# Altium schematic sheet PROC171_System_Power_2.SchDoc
size 431 x 279 mm; Date: Not shown in title block; ApprovedBy: Not shown in title block; CheckedBy: Not shown in title block; Author: Not shown in title block; CompanyName: Not shown in title block; Engineer: Not shown in title block; Organization: Not shown in title block; Address1: Not shown in title block; Address2: Not shown in title block; Address3: Not shown in title block; Address4: Not shown in title block; DocumentNumber: 4; Revision: Use project parameter SCH_Rev; SheetNumber: 4; SheetTotal: 27; PageSetup: Record=PageOptions¦CenterHorizontal=True¦CenterVertical=True¦PrintScale=1.00¦XCorrection=1.00¦YCorrection=1.00¦PrintKind=0¦BorderSize=5000000¦LeftOffset=0¦BottomOffset=0¦Orientation=2¦PaperLength=1000¦PaperWidth=1000¦Scale=100¦PaperSource=15¦PrintQuality=600¦MediaType=1¦DitherType=10¦PaperKind=Letter¦PrintScaleMode=1
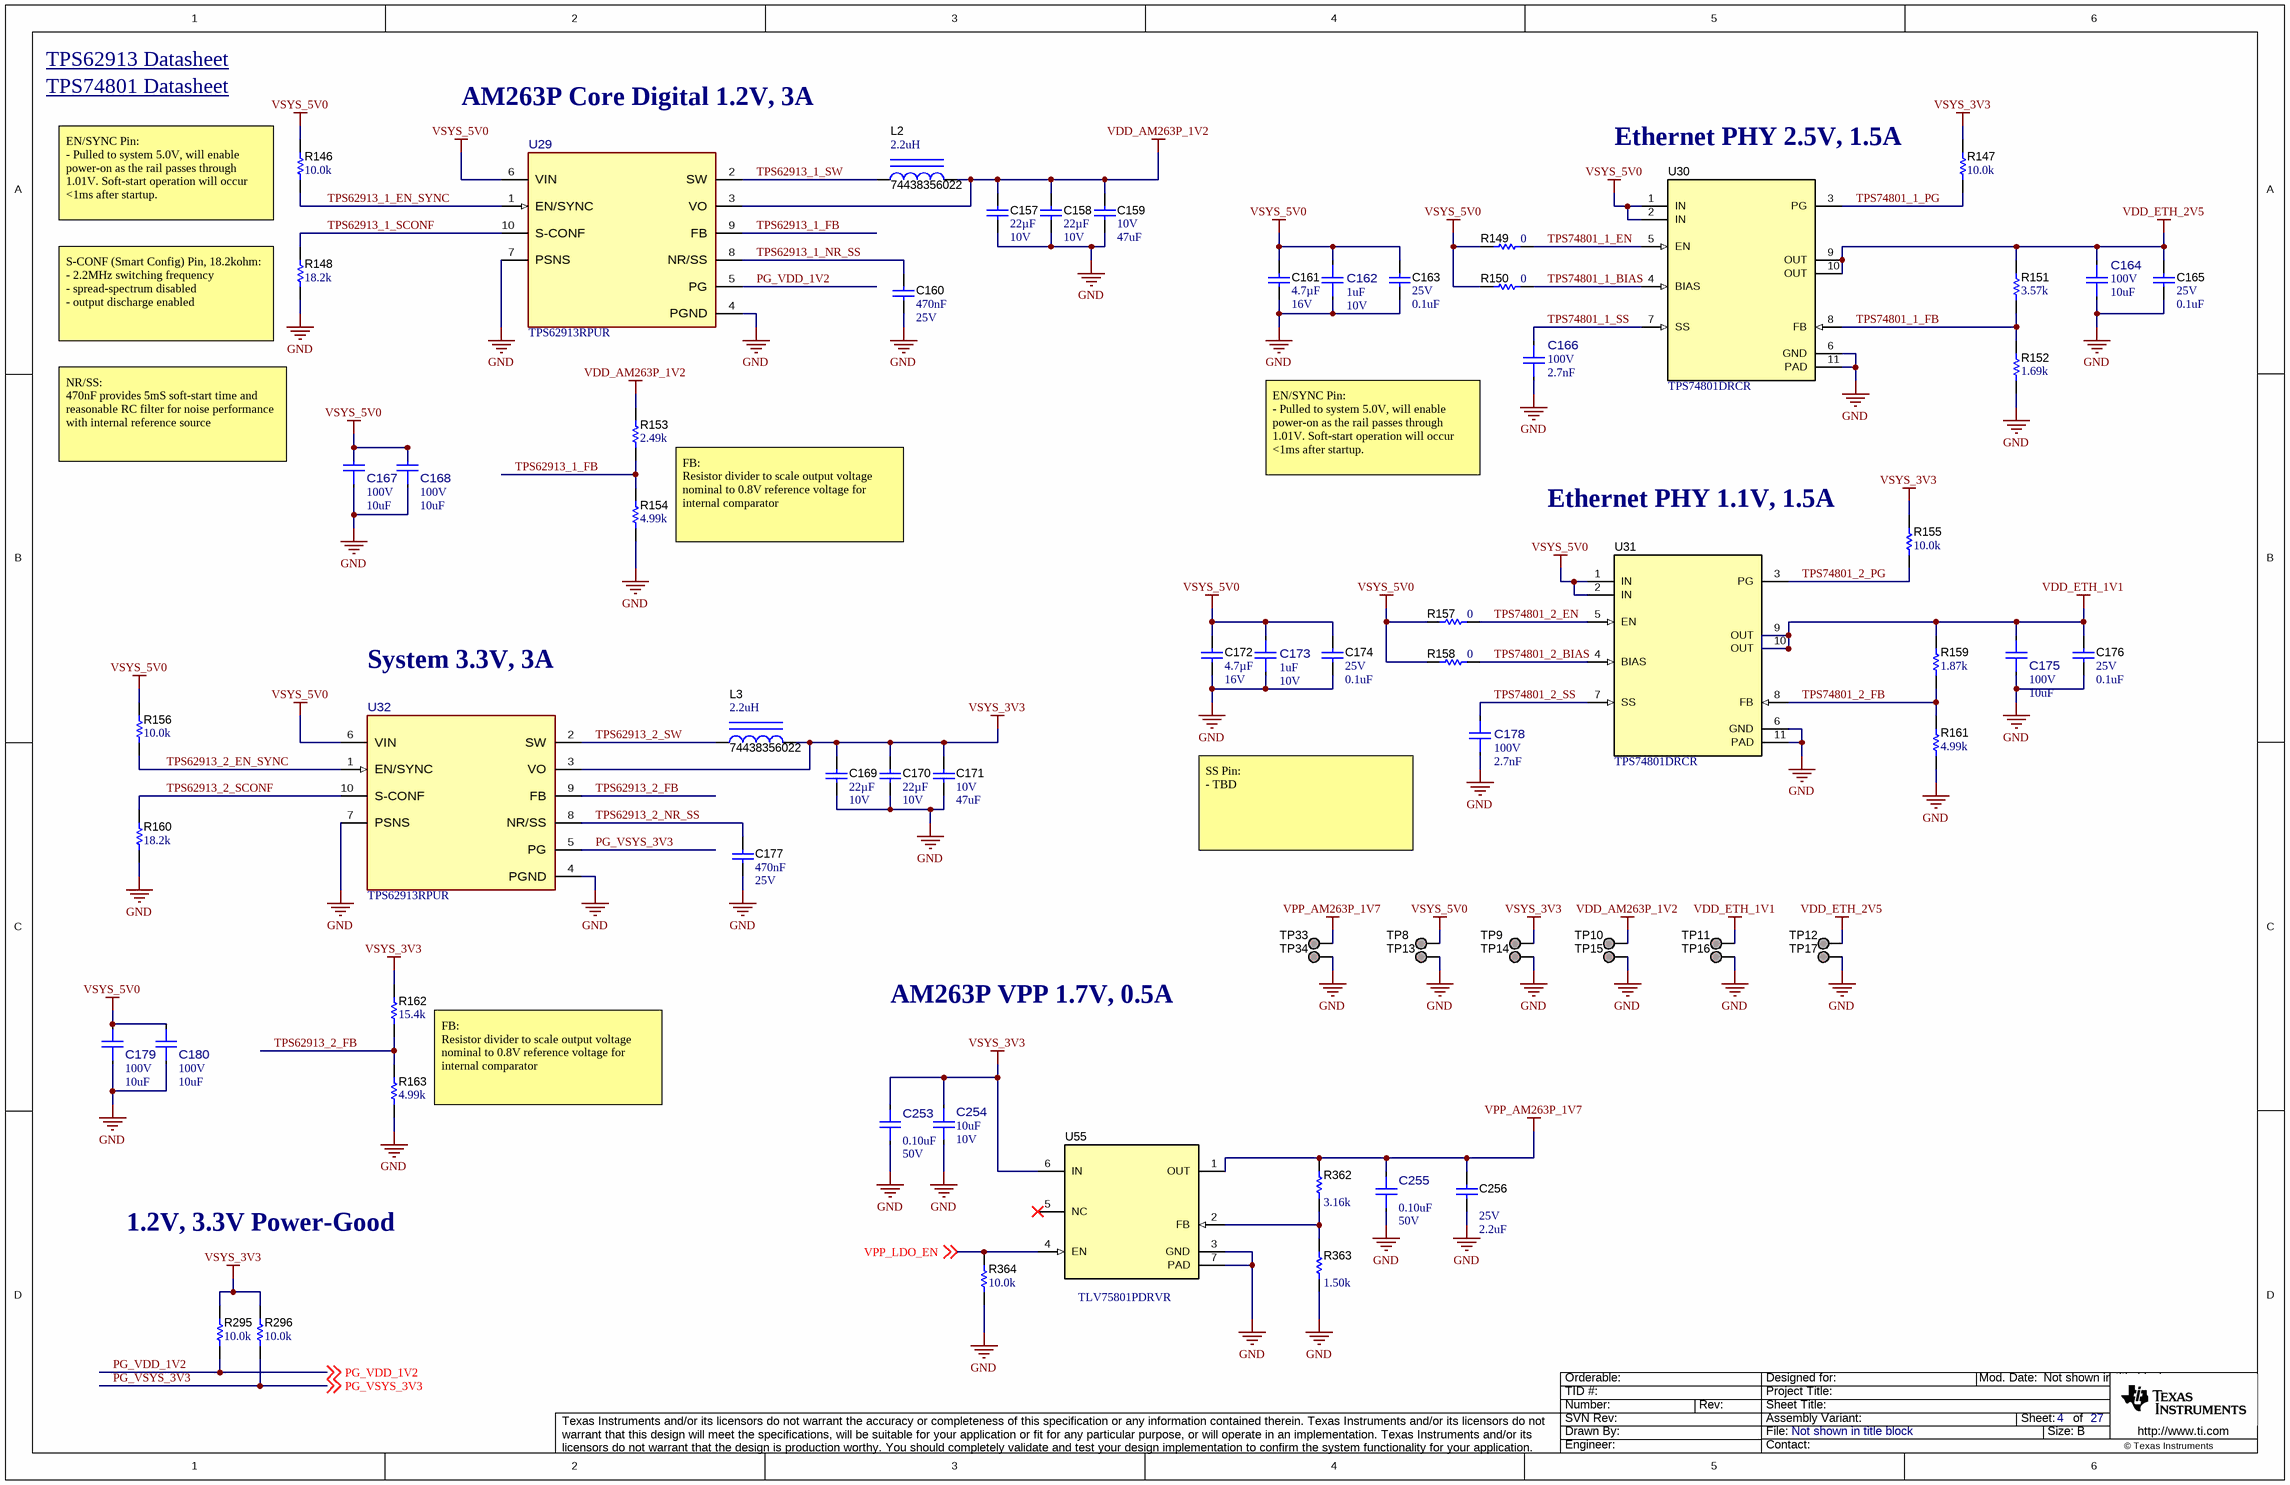
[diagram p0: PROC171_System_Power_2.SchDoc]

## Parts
C157  Cap_F: 22µF  VDC_V: 10V  [0805_HV]  (hidden comment: GRM21BZ71A226ME15L)
C158  Cap_F: 22µF  VDC_V: 10V  [0805_HV]  (hidden comment: GRM21BZ71A226ME15L)
C159  VDC_V: 10V  ValueDisplayed: 47uF  [1210_270]  (hidden comment: GRM32ER71A476ME15L)
C160  Cap_F: 470nF  VDC_V: 25V  [0603]  (hidden comment: GRM188R71E474KA12D)
C161  Cap_F: 4.7µF  VDC_V: 16V  [0603]  (hidden comment: GRM188Z71C475KE21D)
C162  ValueDisplayed: 1uF  VDC_V: 10V  [FP-GRM155C71A105KE11D_0402-MFG]  (hidden comment: GRM155C71A105KE11D)
C163  VDC_V: 25V  ValueDisplayed: 0.1uF  [0402]  (hidden comment: GRM155R71E104KE14D)
C164  VDC_V: 100V  ValueDisplayed: 10uF  [FP-GRM32EC72A106KE05L_1210-MFG]  (hidden comment: GRM32EC72A106KE05L)
C165  VDC_V: 25V  ValueDisplayed: 0.1uF  [0402]  (hidden comment: GRM155R71E104KE14D)
C166  VDC_V: 100V  ValueDisplayed: 2.7nF  [FP-GCM155R72A272KA37D_0402-MFG]  (hidden comment: GCM155R72A272KA37D)
C167  VDC_V: 100V  ValueDisplayed: 10uF  [FP-GRM32EC72A106KE05L_1210-MFG]  (hidden comment: GRM32EC72A106KE05L)
C168  VDC_V: 100V  ValueDisplayed: 10uF  [FP-GRM32EC72A106KE05L_1210-MFG]  (hidden comment: GRM32EC72A106KE05L)
C169  Cap_F: 22µF  VDC_V: 10V  [0805_HV]  (hidden comment: GRM21BZ71A226ME15L)
C170  Cap_F: 22µF  VDC_V: 10V  [0805_HV]  (hidden comment: GRM21BZ71A226ME15L)
C171  VDC_V: 10V  ValueDisplayed: 47uF  [1210_270]  (hidden comment: GRM32ER71A476ME15L)
C172  Cap_F: 4.7µF  VDC_V: 16V  [0603]  (hidden comment: GRM188Z71C475KE21D)
C173  ValueDisplayed: 1uF  VDC_V: 10V  [FP-GRM155C71A105KE11D_0402-MFG]  (hidden comment: GRM155C71A105KE11D)
C174  VDC_V: 25V  ValueDisplayed: 0.1uF  [0402]  (hidden comment: GRM155R71E104KE14D)
C175  VDC_V: 100V  ValueDisplayed: 10uF  [FP-GRM32EC72A106KE05L_1210-MFG]  (hidden comment: GRM32EC72A106KE05L)
C176  VDC_V: 25V  ValueDisplayed: 0.1uF  [0402]  (hidden comment: GRM155R71E104KE14D)
C177  Cap_F: 470nF  VDC_V: 25V  [0603]  (hidden comment: GRM188R71E474KA12D)
C178  VDC_V: 100V  ValueDisplayed: 2.7nF  [FP-GCM155R72A272KA37D_0402-MFG]  (hidden comment: GCM155R72A272KA37D)
C179  VDC_V: 100V  ValueDisplayed: 10uF  [FP-GRM32EC72A106KE05L_1210-MFG]  (hidden comment: GRM32EC72A106KE05L)
C180  VDC_V: 100V  ValueDisplayed: 10uF  [FP-GRM32EC72A106KE05L_1210-MFG]  (hidden comment: GRM32EC72A106KE05L)
C253  ValueDisplayed: 0.10uF  VDC_V: 50V  [FP-GRM155R71H104KE14D_0402-MFG]  (hidden comment: GRM155R71H104KE14D)
C254  ValueDisplayed: 10uF  VDC_V: 10V  [FP-KGM05CR51A106MH_0402-MFG]  (hidden comment: KGM05CR51A106MH)
C255  ValueDisplayed: 0.10uF  VDC_V: 50V  [FP-GRM155R71H104KE14D_0402-MFG]  (hidden comment: GRM155R71H104KE14D)
C256  VDC_V: 25V  ValueDisplayed: 2.2uF  [0402_070]  (hidden comment: GRM155R61E225KE11D)
L2  74438356022  ValueDisplayed: 2.2uH  [WE-MAPI_4020]
L3  74438356022  ValueDisplayed: 2.2uH  [WE-MAPI_4020]
R146  ValueDisplayed: 10.0k  [0402]  (hidden comment: ERJ-2RKF1002X)
R147  ValueDisplayed: 10.0k  [0402]  (hidden comment: ERJ-2RKF1002X)
R148  ValueDisplayed: 18.2k  [0805_HV]  (hidden comment: ERJ-6ENF1822V)
R149  ValueDisplayed: 0  [0402]  (hidden comment: ERJ-2GE0R00X)
R150  ValueDisplayed: 0  [0402]  (hidden comment: ERJ-2GE0R00X)
R151  ValueDisplayed: 3.57k  [0402]  (hidden comment: CRCW04023K57FKED)
R152  ValueDisplayed: 1.69k  [0402]  (hidden comment: CRCW04021K69FKED)
R153  ValueDisplayed: 2.49k  [0402]  (hidden comment: CRCW04022K49FKED)
R154  ValueDisplayed: 4.99k  [0402]  (hidden comment: CRCW04024K99FKED)
R155  ValueDisplayed: 10.0k  [0402]  (hidden comment: ERJ-2RKF1002X)
R156  ValueDisplayed: 10.0k  [0402]  (hidden comment: ERJ-2RKF1002X)
R157  ValueDisplayed: 0  [0402]  (hidden comment: ERJ-2GE0R00X)
R158  ValueDisplayed: 0  [0402]  (hidden comment: ERJ-2GE0R00X)
R159  ValueDisplayed: 1.87k  [0402]  (hidden comment: CRCW04021K87FKED)
R160  ValueDisplayed: 18.2k  [0805_HV]  (hidden comment: ERJ-6ENF1822V)
R161  ValueDisplayed: 4.99k  [0402]  (hidden comment: CRCW04024K99FKED)
R162  ValueDisplayed: 15.4k  [0402]  (hidden comment: CRCW040215K4FKED)
R163  ValueDisplayed: 4.99k  [0402]  (hidden comment: CRCW04024K99FKED)
R295  ValueDisplayed: 10.0k  [0402]  (hidden comment: ERJ-2RKF1002X)
R296  ValueDisplayed: 10.0k  [0402]  (hidden comment: ERJ-2RKF1002X)
R362  ValueDisplayed: 3.16k  [0603]  (hidden comment: RC0603FR-073K16L)
R363  ValueDisplayed: 1.50k  [0402]  (hidden comment: CRCW04021K50FKED)
R364  ValueDisplayed: 10.0k  [0402]  (hidden comment: ERJ-2RKF1002X)
TP8  TESTPOINT  [TP_25MIL-SMT]  (value not drawn)  (no BOM)
TP9  TESTPOINT  [TP_25MIL-SMT]  (value not drawn)  (no BOM)
TP10  TESTPOINT  [TP_25MIL-SMT]  (value not drawn)  (no BOM)
TP11  TESTPOINT  [TP_25MIL-SMT]  (value not drawn)  (no BOM)
TP12  TESTPOINT  [TP_25MIL-SMT]  (value not drawn)  (no BOM)
TP13  TESTPOINT  [TP_25MIL-SMT]  (value not drawn)  (no BOM)
TP14  TESTPOINT  [TP_25MIL-SMT]  (value not drawn)  (no BOM)
TP15  TESTPOINT  [TP_25MIL-SMT]  (value not drawn)  (no BOM)
TP16  TESTPOINT  [TP_25MIL-SMT]  (value not drawn)  (no BOM)
TP17  TESTPOINT  [TP_25MIL-SMT]  (value not drawn)  (no BOM)
TP33  TESTPOINT  [TP_25MIL-SMT]  (value not drawn)  (no BOM)
TP34  TESTPOINT  [TP_25MIL-SMT]  (value not drawn)  (no BOM)
U29  TPS62913RPUR  [RPU0010A-MFG]
U30  TPS74801DRCR  [DRC0010J]
U31  TPS74801DRCR  [DRC0010J]
U32  TPS62913RPUR  [RPU0010A-MFG]
U55  TLV75801PDRVR  [DRV0006A]

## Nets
GND: C157.2 C158.2 C159.2 C160.2 C161.2 C162.1 C163.2 C164.1 C165.2 C166.1 C167.1 C168.1 C169.2 C170.2 C171.2 C172.2 C173.1 C174.2 C175.1 C176.2 C177.2 C178.1 C179.1 C180.1 C253.1 C254.2 C255.1 C256.2 R148.1 R152.1 R154.1 R160.1 R161.1 R163.1 R363.1 R364.1 TP13.1 TP14.1 TP15.1 TP16.1 TP17.1 TP34.1 U29.4(PGND) U29.7(PSNS) U30.6(GND) U30.11(PAD) U31.6(GND) U31.11(PAD) U32.4(PGND) U32.7(PSNS) U55.3(GND) U55.7(PAD)
VDD_AM263P_1V2: C157.1 C158.1 C159.1 L2.2 R153.2 TP10.1 U29.3(VO)
VDD_ETH_1V1: C175.2 C176.1 R159.2 TP11.1 U31.9(OUT) U31.10(OUT)
VDD_ETH_2V5: C164.2 C165.1 R151.2 TP12.1 U30.9(OUT) U30.10(OUT)
VPP_AM263P_1V7: C255.2 C256.1 R362.2 TP33.1 U55.1(OUT)
VSYS_3V3: C169.1 C170.1 C171.1 C253.2 C254.1 L3.2 R147.2 R155.2 R162.2 R295.2 R296.2 TP9.1 U32.3(VO) U55.6(IN)
VSYS_5V0: C161.1 C162.2 C163.1 C167.2 C168.2 C172.1 C173.2 C174.1 C179.2 C180.2 R146.2 R149.1 R150.1 R156.2 R157.1 R158.1 TP8.1 U29.6(VIN) U30.1(IN) U30.2(IN) U31.1(IN) U31.2(IN) U32.6(VIN)
PG_VDD_1V2: R295.1 U29.5(PG) ; off-sheet PG_VDD_1V2
PG_VSYS_3V3: R296.1 U32.5(PG) ; off-sheet PG_VSYS_3V3
TPS62913_1_EN_SYNC: R146.1 U29.1(EN/SYNC)
TPS62913_1_FB: R153.1 R154.2 U29.9(FB)
TPS62913_1_NR_SS: C160.1 U29.8(NR/SS)
TPS62913_1_SCONF: R148.2 U29.10(S-CONF)
TPS62913_1_SW: L2.1 U29.2(SW)
TPS62913_2_EN_SYNC: R156.1 U32.1(EN/SYNC)
TPS62913_2_FB: R162.1 R163.2 U32.9(FB)
TPS62913_2_NR_SS: C177.1 U32.8(NR/SS)
TPS62913_2_SCONF: R160.2 U32.10(S-CONF)
TPS62913_2_SW: L3.1 U32.2(SW)
TPS74801_1_BIAS: R150.2 U30.4(BIAS)
TPS74801_1_EN: R149.2 U30.5(EN)
TPS74801_1_FB: R151.1 R152.2 U30.8(FB)
TPS74801_1_PG: R147.1 U30.3(PG)
TPS74801_1_SS: C166.2 U30.7(SS)
TPS74801_2_BIAS: R158.2 U31.4(BIAS)
TPS74801_2_EN: R157.2 U31.5(EN)
TPS74801_2_FB: R159.1 R161.2 U31.8(FB)
TPS74801_2_PG: R155.1 U31.3(PG)
TPS74801_2_SS: C178.2 U31.7(SS)
VPP_LDO_EN: R364.2 U55.4(EN) ; off-sheet VPP_LDO_EN
NetR362_1: R362.1 R363.2 U55.2(FB)

Not connected (* = marked no-connect by the designer): U55 5(NC)*

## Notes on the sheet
- TPS74801 Datasheet <https://www.ti.com/store/ti/en/p/product/?p=TPS74801DRCR>
- TPS62913 Datasheet <https://www.ti.com/product/TPS62913>
- AM263P Core Digital 1.2V, 3A
- Ethernet PHY 2.5V, 1.5A
- (near R146) EN/SYNC Pin:
  - Pulled to system 5.0V, will enable power-on as the rail passes through 1.01V. Soft-start operation will occur <1ms after startup.
- (near R148) S-CONF (Smart Config) Pin, 18.2kohm:
  - 2.2MHz switching frequency
  - spread-spectrum disabled
  - output discharge enabled
- NR/SS:
  470nF provides 5mS soft-start time and reasonable RC filter for noise performance with internal reference source
- EN/SYNC Pin:
  - Pulled to system 5.0V, will enable power-on as the rail passes through 1.01V. Soft-start operation will occur <1ms after startup.
- FB:
  Resistor divider to scale output voltage nominal to 0.8V reference voltage for internal comparator
- Ethernet PHY 1.1V, 1.5A
- System 3.3V, 3A
- SS Pin:
  - TBD
- AM263P VPP 1.7V, 0.5A
- 1.2V, 3.3V Power-Good

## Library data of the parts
C157 C158 C169 C170 = CMP-0008377-2: CAP, CERM, 22 uF, 10 V, +/- 20%, X7R, 0805; Manufacturer: MuRata; SizeY_mm: 1.25; Cap_Case: 0805; SizeArea_mm2: 2.5; AEC Qualified: N; AEC Category: Q200; ValueDisplayed: 22uF; TaMin_C: -55°C; SizeAreaWB_mm2: 6.75; Value1: Unknown; U/M: EA; Value: 22uF; TaMax_C: 125°C; SizeZ_mm: 1.45; SizeX_mm: 2
C159 C171 = CMP-0009221-2: CAP, CERM, 47 uF, 10 V, +/- 20%, X7R, 1210; Manufacturer: MuRata; TaMin_C: -55°C; Polarized: N; SizeAreaWB_mm2: 14.7; Value1: Unknown; U/M: EA; Value: 47uF; TaMax_C: 125°C; SizeZ_mm: 2.7; SizeX_mm: 3.2; SizeY_mm: 2.5; Cap_Case: 1210; SizeArea_mm2: 8; Cap_F: 47µF; AEC Category: Q200
C160 C177 = CMP-0007424-4: CAP, CERM, 0.47 uF, 25 V, +/- 10%, X7R, 0603; Manufacturer: MuRata; TaMin_C: -55°C; Polarized: N; SizeAreaWB_mm2: 4.68; Value1: Unknown; U/M: EA; Value: 0.47uF; TaMax_C: 125°C; SizeZ_mm: 1; SizeX_mm: 1.6; SizeY_mm: 0.8; SizeArea_mm2: 1.28; AEC Category: Q200
C161 C172 = CMP-0064936-4: CAP, CERM, 4.7 uF, 16 V,+/- 10%, X7R, 0603; Manufacturer: MuRata; TaMin_C: -55°C; Polarized: N; SizeAreaWB_mm2: 4.68; Value1: Unknown; U/M: EA; Value: 4.7uF; TaMax_C: 125°C; SizeZ_mm: 1; SizeX_mm: 1.6; SizeY_mm: 0.8; SizeArea_mm2: 1.28; AEC Category: Q200
C162 C173 = CMP-0035346-1: 1µF ±10% 10V Ceramic Capacitor X7S 0402 (1005 Metric); Manufacturer: Murata; AEC Qualified: No; SizeZ_mm: 0.6mm; TempCo: 22%
C163 C165 C174 C176 = CMP-0006659-2: CAP, CERM, 0.1 uF, 25 V, +/- 10%, X7R, 0402; Manufacturer: MuRata; TaMin_C: -55°C; Polarized: N; SizeAreaWB_mm2: 3; Value1: Unknown; U/M: EA; Value: 0.1uF; TaMax_C: 125°C; SizeZ_mm: 0.6; SizeX_mm: 1; SizeY_mm: 0.5; Cap_F: 100nF; AEC Category: Q200
C164 C167 C168 C175 C179 C180 = CMP-0087970-1: 10µF ±10% 100V Ceramic Capacitor X7S 1210 (3225 Metric); Manufacturer: Murata; TempCo: 22%; SizeZ_mm: 2.7mm; AEC Qualified: No; Symbol Name: SYM-GRM32EC72A106KE05L
C166 C178 = CMP-0035196-1: Ceramic Capacitor for Automotive 2.7nF ±10% 100VDC X7R 0402 Paper T/R; Manufacturer: Murata; TempCo: 15%; Tolerance_%: 0.1%; SizeZ_mm: 0.55mm; AEC Qualified: Yes; AEC Grade: Grade 1
C253 C255 = CMP-0096855-1: Chip Multilayer Ceramic Capacitors for General Purpose, 0402, 0.10uF, X7R, 15%, 10%, 50V; Manufacturer: Murata; SizeZ_mm: 0.55mm; Value: 100nF; AEC Qualified: No
C254 = CMP-0043010-1: 10 µF ±20% 10V Ceramic Capacitor X5R 0402 (1005 Metric); Manufacturer: KYOCERA AVX; AEC Qualified: No; Cap_F: 10µF; SizeZ_mm: 0.7mm; TempCo: 15%; Value: 10µF
C256 = CMP-0006610-2: CAP, CERM, 2.2 uF, 25 V, +/- 10%, X5R, 0402; Manufacturer: MuRata; TaMin_C: -55°C; Polarized: N; SizeAreaWB_mm2: 3; Value1: Unknown; U/M: EA; Value: 2.2uF; TaMax_C: 85°C; SizeZ_mm: 0.7; SizeX_mm: 1; SizeY_mm: 0.5; Cap_Case: 0402; Cap_F: 2.2µF; AEC Category: Q200
L2 L3 = CMP-0064169-1: Inductor, Shielded, 2.2 uH, 4.7 A, 0.029 ohm, SMD; Manufacturer: Wurth Elektronik; Isat: 6.2A @ 20% inductance drop; Irms: 4.7A @ 40C rise; Green_Lifecycle: Active; SizeAreaWB_mm2: 26.01; DCR_ohm: 29m; Green_REACh: Passed; Value: 2.2uH; Imax_A: 4.7A; SizeZ_mm: 2.1; SizeX_mm: 4.1; SizeArea_mm2: 16.81; Ind_H: 2.2µH; AEC Qualified: N; AEC Category: Q200
R146 R147 R155 R156 R295 R296 R364 = CMP-0026658-1: RES, 10.0 k, 1%, 0.1 W, 0402; Manufacturer: Panasonic; Power_W: 100mW; TempCo: 100 ppm/C; Value_Code: 10k0; U/M: EA; Value: 10.0k; EIA_Code: E96; Res_ohm: 10k; SizeX_mm: 1; SizeY_mm: 0.5; SizeZ_mm: 0.6; Value2: 0.1W; VDC_V: 50V; AEC Category: Q200
R148 R160 = CMP-0021602-3: RES, 18.2 k, 1%, 0.125 W, AEC-Q200 Grade 0, 0805; Manufacturer: Panasonic; Power_W: 125mW; TempCo: 100 ppm/C; Value_Code: 18k2; Value: 18.2k; EIA_Code: E96; SizeX_mm: 2; SizeY_mm: 1.25; SizeZ_mm: 1.45; Value2: 0.125W; SizeArea_mm2: 2.5; AEC Qualified: Y; AEC Category: Q200; AEC Grade: 0; SizeAreaWB_mm2: 6.75
R149 R150 R157 R158 = CMP-0026992-3: RES, 0, 5%, 0.1 W, AEC-Q200 Grade 0, 0402; Manufacturer: Panasonic; Power_W: 100mW; TempCo: 600 ppm/C; Value_Code: 0000; Value: 0; EIA_Code: E24; SizeX_mm: 1; SizeY_mm: 0.5; SizeZ_mm: 0.6; Value2: 0.1W; AEC Qualified: Y; VDC_V: 50V; AEC Category: Q200; SizeAreaWB_mm2: 3
R151 = CMP-0026336-2: RES, 3.57 k, 1%, 0.063 W, AEC-Q200 Grade 0, 0402; Manufacturer: Vishay-Dale; Power_W: 63mW; TempCo: 100 ppm/C; Value_Code: 3k57; Value: 3.57k; EIA_Code: E96; SizeX_mm: 1; SizeY_mm: 0.5; SizeZ_mm: 0.6; Value2: 0.063W; AEC Qualified: Y; VDC_V: 50V; AEC Category: Q200; AEC Grade: 0
R152 = CMP-0026093-3: RES, 1.69 k, 1%, 0.063 W, AEC-Q200 Grade 0, 0402; Manufacturer: Vishay-Dale; Power_W: 63mW; TempCo: 100 ppm/C; Value_Code: 1k69; Value: 1.69k; EIA_Code: E96; SizeX_mm: 1; SizeY_mm: 0.5; SizeZ_mm: 0.6; Value2: 0.063W; AEC Qualified: Y; VDC_V: 50V; AEC Category: Q200; AEC Grade: 0
R153 = CMP-0026237-2: RES, 2.49 k, 1%, 0.063 W, AEC-Q200 Grade 0, 0402; Manufacturer: Vishay-Dale; Power_W: 63mW; TempCo: 100 ppm/C; Value_Code: 2k49; Value: 2.49k; EIA_Code: E96; SizeX_mm: 1; SizeY_mm: 0.5; SizeZ_mm: 0.6; Value2: 0.063W; AEC Qualified: Y; VDC_V: 50V; AEC Category: Q200; AEC Grade: 0
R154 R161 R163 = CMP-0026414-2: RES, 4.99 k, 1%, 0.063 W, AEC-Q200 Grade 0, 0402; Manufacturer: Vishay-Dale; Power_W: 63mW; TempCo: 100 ppm/C; Value_Code: 4k99; Value: 4.99k; EIA_Code: E96; SizeX_mm: 1; SizeY_mm: 0.5; SizeZ_mm: 0.6; Value2: 0.063W; AEC Qualified: Y; VDC_V: 50V; AEC Category: Q200; AEC Grade: 0
R159 = CMP-0026097-2: RES, 1.87 k, 1%, 0.063 W, AEC-Q200 Grade 0, 0402; Manufacturer: Vishay-Dale; Power_W: 63mW; TempCo: 100 ppm/C; Value_Code: 1k87; Value: 1.87k; EIA_Code: E96; SizeX_mm: 1; SizeY_mm: 0.5; SizeZ_mm: 0.6; Value2: 0.063W; AEC Qualified: Y; VDC_V: 50V; AEC Category: Q200; AEC Grade: 0
R162 = CMP-0026028-3: RES, 15.4 k, 1%, 0.063 W, AEC-Q200 Grade 0, 0402; Manufacturer: Vishay-Dale; Power_W: 63mW; TempCo: 100 ppm/C; Value_Code: 15k4; Value: 15.4k; EIA_Code: E96; SizeX_mm: 1; SizeY_mm: 0.5; SizeZ_mm: 0.6; Value2: 0.063W; AEC Qualified: Y; VDC_V: 50V; AEC Category: Q200; AEC Grade: 0
R362 = CMP-0023078-5: RES, 3.16 k, 1%, 0.1 W, 0603; Manufacturer: Yageo; Power_W: 100mW; TempCo: 100 ppm/C; Value_Code: 3k16; Value: 3.16k; EIA_Code: E96; SizeX_mm: 1.6; SizeY_mm: 0.8; SizeZ_mm: 1; Value2: 0.1W; SizeArea_mm2: 1.28; AEC Qualified: N; VDC_V: 75V; AEC Category: Q200; SizeAreaWB_mm2: 4.68
R363 = CMP-0026088-3: RES, 1.50 k, 1%, 0.063 W, AEC-Q200 Grade 0, 0402; Manufacturer: Vishay-Dale; Power_W: 63mW; TempCo: 100 ppm/C; Value_Code: 1k50; Value: 1.50k; EIA_Code: E96; Res_ohm: 1.5k; SizeX_mm: 1; SizeY_mm: 0.5; SizeZ_mm: 0.6; Value2: 0.063W; AEC Qualified: Y; VDC_V: 50V; AEC Category: Q200; AEC Grade: 0
TP8-TP17 TP33 TP34 = CMP-0078143-3: TEST POINT.  No entry in BOM.
U29 U32 = CMP-0089785-1: 3V to 17V, 3A Micro Noise (20µVRMS) and Micro Ripple (200µVPP) buck converter; Manufacturer: Texas Instruments; SizeZ_mm: 1mm; TJmax_C: +150°C; Output Type: AdjustableProgrammable; Switching Frequency: 1/2.2MHz; Max Duty Cycle: 55%; Number Of Outputs: 1; Nominal Supply Current: 5mA; AEC Qualified: No; Output Voltage: 0.8-5.5V; Standoff Height: 0mm
U30 U31 = CMP-0036365-5: Single Output LDO, 1.5A, Adj. (0.8 to 3.6V), Programmable Soft-Start, DRC0010J (VSON-10); Manufacturer: Texas Instruments; SizeArea_mm2: 9; Iq(Typ)(mA): 1; Vout Adj(Max)(V): 3.6; SizeY_mm: 3; Power Good: TRUE; AEC Category: Q200; Accuracy(%): 2; Rating: Catalog; Vdo(Typ)(mV): 60; Vin(Min)(V): 0.8; CompType: IC; Vin(Max)(V): 5.5; Iout(Max)(A): 1.5; AEC Qualified: N; SizeAreaWB_mm2: 16
U55 = CMP-0084398-1: 500-mA LDO, DRV0006A (WSON-6); Manufacturer: Texas Instruments; Alternate PartNumber: TLV75801PDRVT; AEC Qualified: N; Rating: Catalog; SizeX_mm: 2; SizeAreaWB_mm2: 9; SizeArea_mm2: 4; CompType: IC; SizeZ_mm: 0.8; AEC Category: Q200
